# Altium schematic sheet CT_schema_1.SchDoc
size 441 x 258 mm
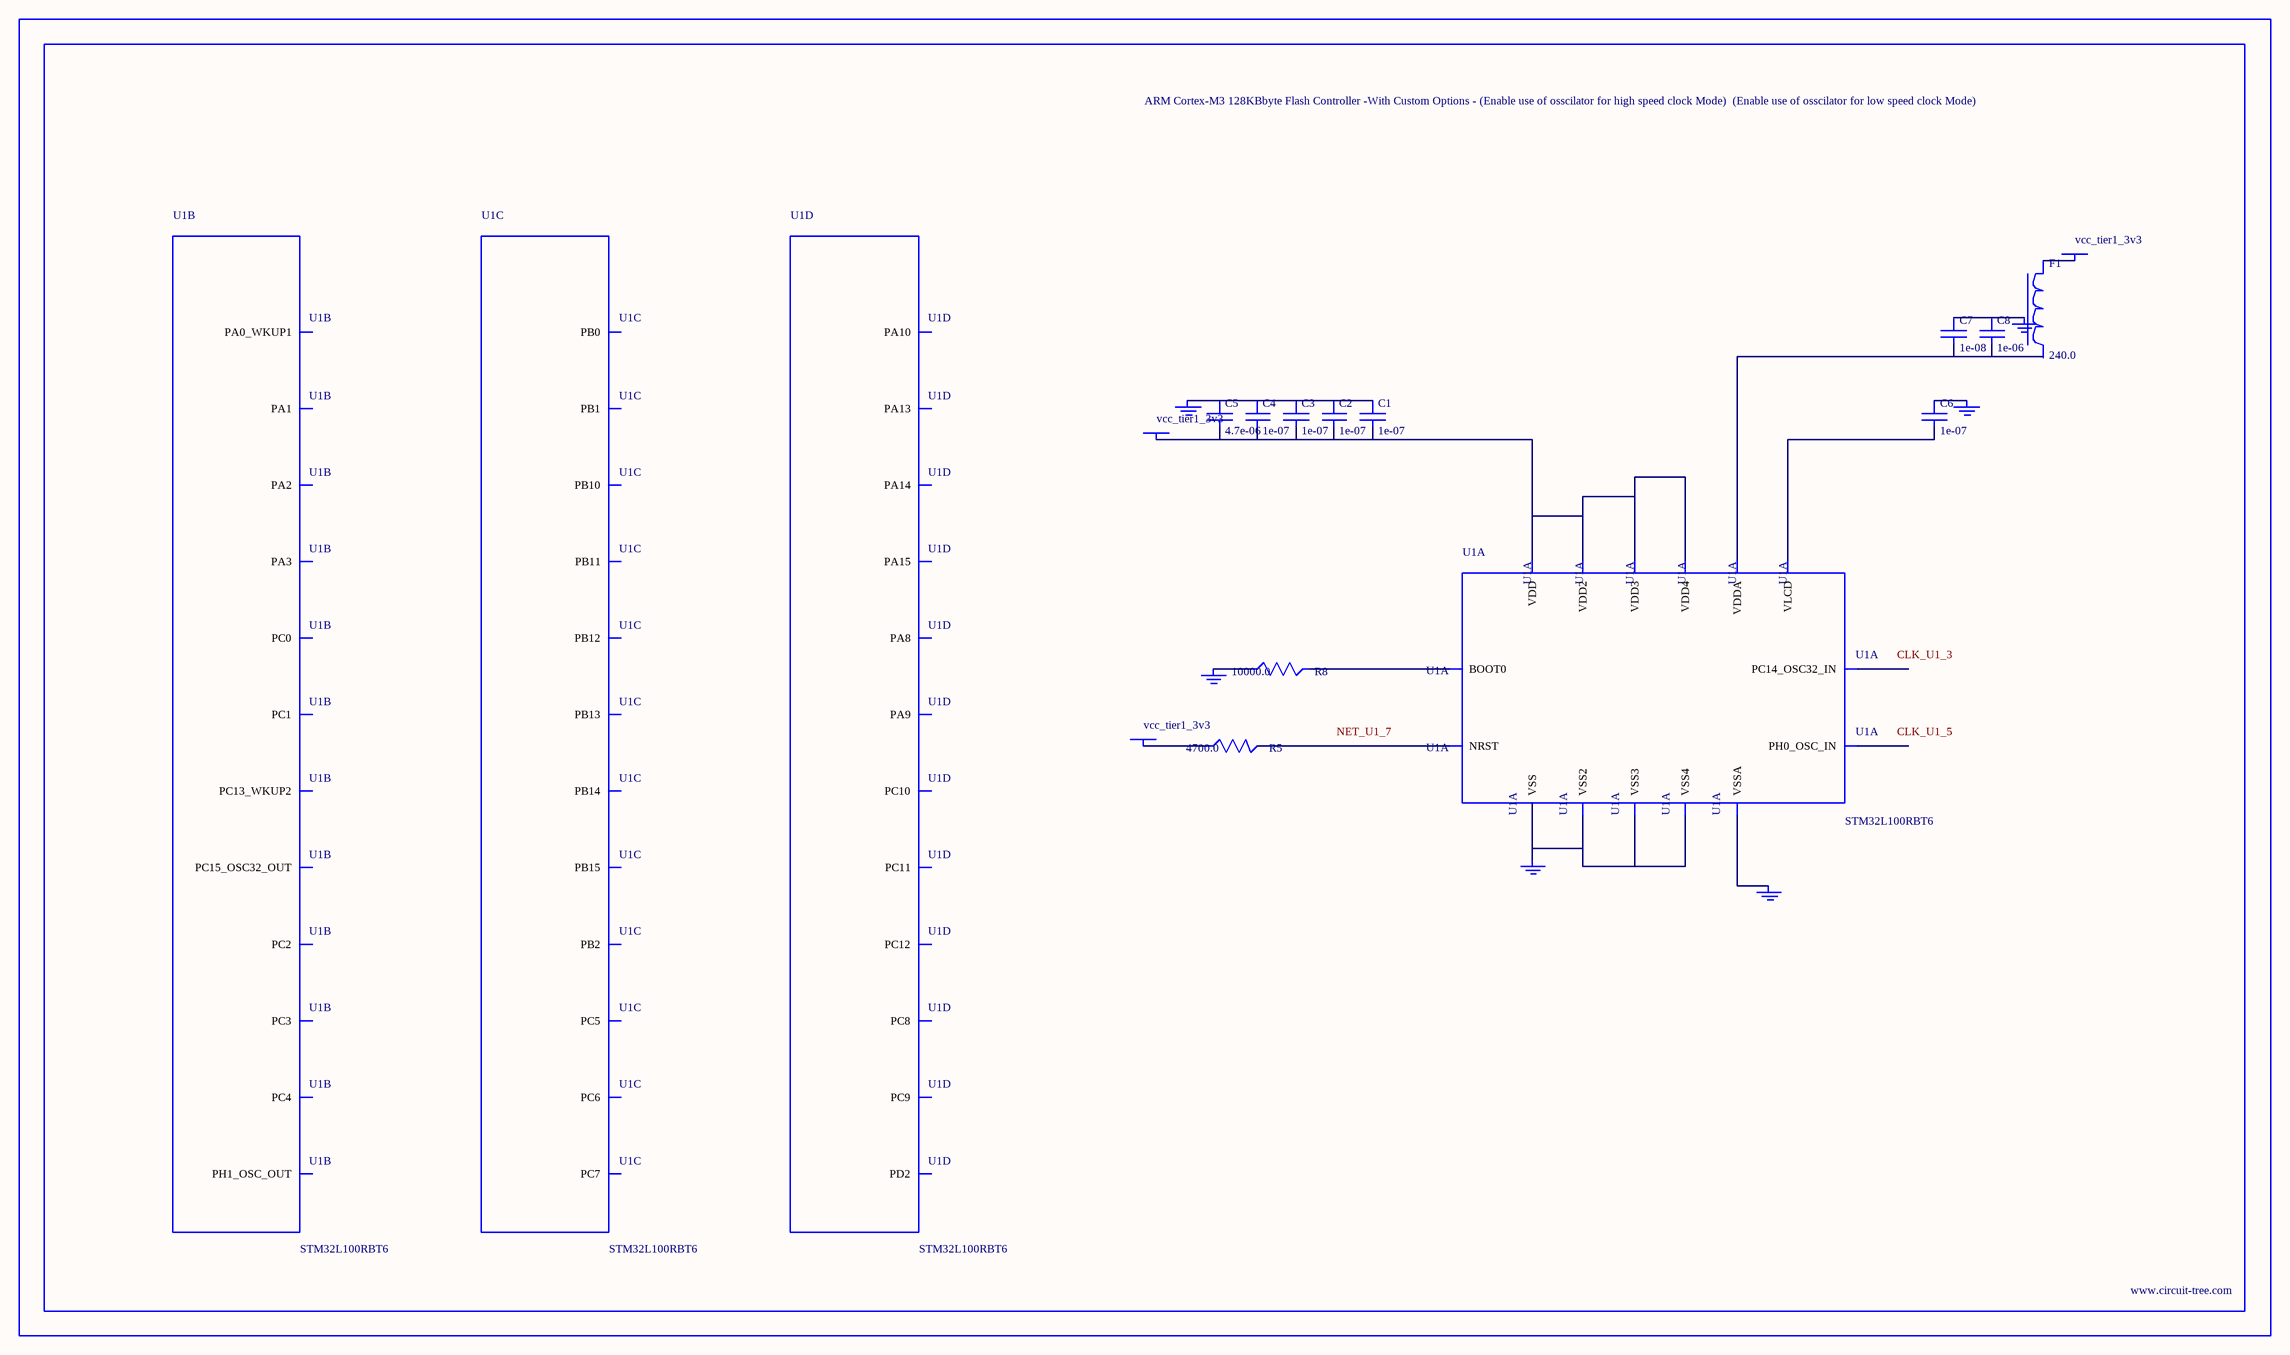
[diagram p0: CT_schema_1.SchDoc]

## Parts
BORDER0  (no value)
C1  1e-07  [C0603]
C2  1e-07  [C0603]
C3  1e-07  [C0603]
C4  1e-07  [C0603]
C5  4.7e-06  [C0603]
C6  1e-07  [C0603]
C7  1e-08  [C0603]
C8  1e-06  [C0603]
F1  240.0  [L0603]
GND_INSTANCE_0_0  (no value)
GND_INSTANCE_0_1  (no value)
GND_INSTANCE_0_2  (no value)
GND_INSTANCE_0_3  (no value)
GND_INSTANCE_0_4  (no value)
GND_INSTANCE_0_5  (no value)
POWER_INSTANCE_0_0  vcc_tier1_3v3
POWER_INSTANCE_0_1  vcc_tier1_3v3
POWER_INSTANCE_0_2  vcc_tier1_3v3
R5  4700.0  [R0603]
R8  10000.0  [R0603]
U1  STM32L100RBT6  [LQFP64]  (parts A,B,C,D of 7)

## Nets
NetC1_1: C1.1 C2.1 C3.1 C4.1 C5.1 GND_INSTANCE_0_3.0(GND)
NetC1_2: C1.2 C2.2 C3.2 C4.2 C5.2 POWER_INSTANCE_0_1.0(PWR) U1.19(VDD) U1.32(VDD2) U1.48(VDD3) U1.64(VDD4)
NetC6_1: C6.1 GND_INSTANCE_0_0.0(GND)
NetC6_2: C6.2 U1.1(VLCD)
NetC7_1: C7.1 C8.1 GND_INSTANCE_0_2.0(GND)
NetC7_2: C7.2 C8.2 U1.13(VDDA)
NetF1_1: F1.1 POWER_INSTANCE_0_0.0(PWR)
NetGND_INSTANCE_0_1_0: GND_INSTANCE_0_1.0(GND) U1.12(VSSA)
NetGND_INSTANCE_0_4_0: GND_INSTANCE_0_4.0(GND) R8.1
NetGND_INSTANCE_0_5_0: GND_INSTANCE_0_5.0(GND) U1.18(VSS) U1.31(VSS2) U1.47(VSS3) U1.63(VSS4)
NetPOWER_INSTANCE_0_2_0: POWER_INSTANCE_0_2.0(PWR) R5.1
NetR5_2: R5.2 U1.7(NRST)
NetR8_2: R8.2 U1.60(BOOT0)

Not connected (* = marked no-connect by the designer): F1 2; U1 2(PC13_WKUP2) 3(PC14_OSC32_IN) 4(PC15_OSC32_OUT) 5(PH0_OSC_IN) 6(PH1_OSC_OUT) 8(PC0) 9(PC1) 10(PC2) 11(PC3) 14(PA0_WKUP1) 15(PA1) 16(PA2) 17(PA3) 24(PC4) 25(PC5) 26(PB0) 27(PB1) 28(PB2) 29(PB10) 30(PB11) 33(PB12) 34(PB13) 35(PB14) 36(PB15) 37(PC6) 38(PC7) 39(PC8) 40(PC9) 41(PA8) 42(PA9) 43(PA10) 46(PA13) 49(PA14) 50(PA15) 51(PC10) 52(PC11) 53(PC12) 54(PD2)

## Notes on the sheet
- Labels drawn without touching a wire or pin: CLK_U1_3, CLK_U1_5, NET_U1_7

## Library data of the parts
BORDER0 = BORDER_PAGE0
C1-C4 C6 = 06035C104K4Z2A
C5 = GRM188R6YA475KE15D
C7 = 06035C103K4Z2A
C8 = C0603C105K3RACTU
F1 = Z0603C241ASMST
GND_INSTANCE_0_0-GND_INSTANCE_0_5 = GND
POWER_INSTANCE_0_0-POWER_INSTANCE_0_2 = PWR
R5 = RC0603JR-074K7L
R8 = RC0603JR-0710KL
